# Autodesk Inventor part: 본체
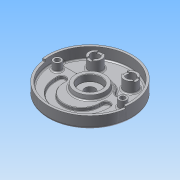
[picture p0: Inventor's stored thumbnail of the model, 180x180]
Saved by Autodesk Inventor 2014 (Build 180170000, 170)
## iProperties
Created: 2015-06
Part Number: 본체
Material: 알루미늄 6061
Document SubType Name: Modeling
Designer: Administrator
Density: 2.71 g/cm^3
Appearance: 알루미늄 - 평지
Mass: 1115.25 g
Surface Area: 1045.8 cm^2
Volume: 411.532 cm^3
Author: Administrator
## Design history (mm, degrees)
sketch "스케치1"
  geometry: C1 r 95 at (0, 0); 1 further point
  constraints: 1 centre point, 1 coincident
  dimensions: "d0" = 190 diameter of C1
extrude "돌출1" new body sketch "스케치1" distance "d1" = 32; taper "d2" = 0 deg
hole "구멍1" diameter "d5" = 180; stored, may be unused: countersink angle "d9" = 90 deg, drill point angle "d11" = 0 deg; dims "d3" = 10, "d4" = 10, "d6" = 6, "d7" = 4, "d8" = 2, "d10" = 25
sketch "스케치2"
  geometry: L1 (-95, 0)-(95, 0); L2 (0, 0)-(-94.075, -13.221); L3 (0, 0)-(94.075, -13.221); C1 r 90 at (0, 0) reference; A1 r 95 centre (0, 0) between (-95, 0) and (95, 0) reference
  constraints: 6 end point, 4 point on circle, 1 coincident, 1 horizontal, 1 midpoint
  dimensions: "d12" = 8 deg angle of L2 L1; "d13" = 8 deg angle of L3 L1
extrude "돌출2" cut sketch "스케치2" distance "d14" = 5; taper "d15" = 0 deg
sketch "스케치3"
  geometry: C1 r 90 at (0, 0) reference; C2 r 42 at (0, 0)
  constraints: 1 centre point, 1 coincident
  dimensions: "d16" = 84 diameter of C2
extrude "돌출3" join sketch "스케치3" distance "d17" = 7; taper "d18" = 0 deg
sketch "스케치4"
  geometry: C1 r 42 at (0, 0) reference; C2 r 35 at (0, 0)
  constraints: 1 centre point, 1 coincident
  dimensions: "d19" = 70 diameter of C2
extrude "돌출4" join sketch "스케치4" distance "d20" = 10; taper "d21" = -10 deg
hole "구멍2" diameter "d24" = 23; stored, may be unused: countersink angle "d28" = 90 deg, drill point angle "d30" = 0 deg; dims "d25" = 6, "d26" = 50, "d27" = 15, "d29" = 23, "d111" = 10, "d112" = 10
sketch "스케치5"
  geometry: C1 r 95 at (0, 0) reference; C2 r 26 at (0, 0)
  constraints: 1 centre point, 1 coincident
  dimensions: "d31" = 52 diameter of C2
extrude "돌출5" join sketch "스케치5" distance "d32" = 11.5; taper "d33" = -15 deg
sketch "스케치6"
  geometry: C1 r 42 at (0, 0) reference; C2 r 15 at (-40, 52); C3 r 15 at (40, 52)
  constraints: 2 centre point, 1 equal radius, 1 horizontal alignment
  dimensions: "d35" = 30 diameter of C2; "d36" = 40 horizontal distance of C2.centre C1.centre; "d37" = 40 horizontal distance of C3.centre C1.centre; "d38" = 52 vertical distance of C3.centre C1.centre
extrude "돌출6" join sketch "스케치6" stored distance "d39" = 11.5; taper "d40" = 0 deg
hole "구멍3" diameter "d43" = 20; stored, may be unused: countersink angle "d47" = 90 deg, drill point angle "d49" = 0 deg; dims "d41" = 10, "d42" = 10, "d44" = 6, "d45" = 50, "d46" = 15, "d48" = 23
hole "구멍4" diameter "d52" = 20; stored, may be unused: countersink angle "d56" = 90 deg, drill point angle "d58" = 0 deg; dims "d50" = 10, "d51" = 10, "d53" = 6, "d54" = 50, "d55" = 15, "d57" = 23
sketch "스케치7"
  geometry: L1 (-6, 13.748)-(-6, 8); L2 (-6, -8)-(-6, -13.748); L3 (6, -13.748)-(6, -8); L4 (6, 8)-(6, 13.748); A1 r 10 centre (0, 0) between (-6, 8) and (-6, -8) reference; A2 r 15 centre (0, 0) between (-6, 13.748) and (-6, -13.748) reference; 1 further point
  constraints: 8 end point, 8 point on circle, 6 parallel, 2 vertical
  dimensions: "d60" = 12 distance between parallel lines of L4 L1; "d61" = 12 distance between parallel lines of L3 L2
extrude "돌출7" cut sketch "스케치7" distance "d62" = 3; taper "d63" = 0 deg
sketch "스케치8"
  geometry: L1 (-13.748, 6)-(-8, 6); L2 (8, 6)-(13.748, 6); L3 (-13.748, -6)-(-8, -6); L4 (8, -6)-(13.748, -6); A1 r 10 centre (0, 0) between (-8, 6) and (8, 6) reference; A2 r 15 centre (0, 0) between (-13.748, 6) and (13.748, 6) reference; 1 further point
  constraints: 8 end point, 8 point on circle, 6 parallel, 2 horizontal
  dimensions: "d65" = 12 distance between parallel lines of L3 L1; "d66" = 12 distance between parallel lines of L4 L2
extrude "돌출8" cut sketch "스케치8" distance "d67" = 3; taper "d68" = 0 deg
sketch "스케치9"
  geometry: L1 (-90, 0)-(90, 0); L2 (-88.566, 16)-(-38.833, 16); L3 (38.833, 16)-(88.566, 16); A1 r 42 centre (0, 0) between (-38.833, 16) and (38.833, 16) reference; A2 r 90 centre (0, 0) between (-90, 0) and (-88.566, 16) reference; 1 further point
  constraints: 6 end point, 6 point on circle, 2 parallel, 1 coincident, 1 horizontal, 1 midpoint
  dimensions: "d70" = 16 distance between parallel lines of L1 L2; "d71" = 16 distance between parallel lines of L1 L3
extrude "돌출9" join sketch "스케치9" distance "d72" = 7; taper "d73" = 0 deg
sketch "스케치10"
  geometry: C1 r 35 at (0, 0) reference; C2 r 9 at (-74, 0); C3 r 9 at (74, 0)
  constraints: 2 centre point, 2 horizontal alignment
  dimensions: "d74" = 74 distance of C1.centre C2.centre; "d75" = 74 distance of C3.centre C1.centre; "d76" = 18 diameter of C2; "d77" = 18 diameter of C3
extrude "돌출10" join sketch "스케치10" stored distance "d78" = 7; taper "d79" = 0 deg
sketch "스케치11"
  geometry: C1 r 9 at (-74, 0) reference; C2 r 9 at (74, 0) reference; 2 further points
  constraints: 2 coincident
hole "구멍5" sketch "스케치11" at (-74, 0), (74, 0) diameter "d80" = 11; stored, may be unused: countersink angle "d84" = 90 deg, drill point angle "d86" = 0 deg; dims "d81" = 6, "d82" = 18, "d83" = 11, "d85" = 23
sketch "스케치12"
  geometry: L1 (88.566, 16)-(38.833, 16) reference; L2 (-40.21, 0)-(36.332, 0); L3 (-59, -19)-(59, -19); L4 (-58.788, -14)-(58.788, -14); L5 (-59, -19)-(-59, -14); L6 (-41, -19)-(-41, -14); L7 (41, -19)-(41, -14); L8 (59, -19)-(59, -14); L9 (-50, -19)-(-50, -14); A1 r 59 centre (0, -19) between (-59, -19) and (59, -19); A2 r 41 centre (0, -19) between (-41, -19) and (41, -19); A3 r 9 centre (-50, -14) between (-41, -14) and (-59, -14); A4 r 9 centre (50, -14) between (59, -14) and (41, -14); 4 further points
  constraints: 16 end point, 8 point on circle, 7 parallel, 7 point on line, 5 coincident, 4 centre point, 4 tangent, 1 midpoint, 1 perpendicular, 1 vertical alignment
  dimensions: "d90" = 19 distance from line of point (0, -19) L2; "d91" = 59 radius of A1; "d94" = 5 distance between parallel lines of L3 L4; "d95" = 41 radius of A2; "d97" = 18 diameter of A3; "d99" = 18 diameter of A4; "d102" = 35 distance from line of L9.start L1; "d103" = 0.21225 distance from line of L4.end L8; "d104" = 22.6682 distance from line of L2.end L8; "d105" = 99.21034 distance from line of L2.start L8; "d106" = 117.78775 distance from line of L4.start L8
extrude "돌출11" cut sketch "스케치12" distance "d100" = 7; taper "d101" = 0 deg
sketch "스케치13"
  geometry: C1 r 95 at (0, 0) reference; C2 r 74 at (0, 0); C3 r 68 at (0, 0)
  constraints: 2 centre point, 2 coincident, 1 other
  dimensions: "d107" = 148 diameter of C2; "d108" = 136 diameter of C3
feature "엠보싱1" sketch "스케치13" dims "d109" = 0.5, "d110" = 0
hole "구멍6" diameter "d115" = 23; stored, may be unused: countersink angle "d119" = 90 deg, drill point angle "d121" = 0 deg; dims "d113" = 10, "d114" = 10, "d116" = 6, "d117" = 18, "d118" = 11, "d120" = 23
fillet "모깎기1" dims "d122" = 10
fillet "모깎기2" dims "d123" = 3
fillet "모깎기3" dims "d124" = 3
fillet "모깎기4" dims "d125" = 1
fillet "모깎기5" dims "d126" = 3
fillet "모깎기6" dims "d127" = 3
fillet "모깎기7" dims "d128" = 0.3
chamfer "모따기1" distance "d129" = 1; stored, may be unused: second distance "d130" = 2, angle "d131" = 45 deg
fillet "모깎기8" dims "d132" = 5
node "솔리드1"
other parameters: "d59" = 12, "d64" = 12, "d69" = 16, "d92" = 41, "d93" = 5
